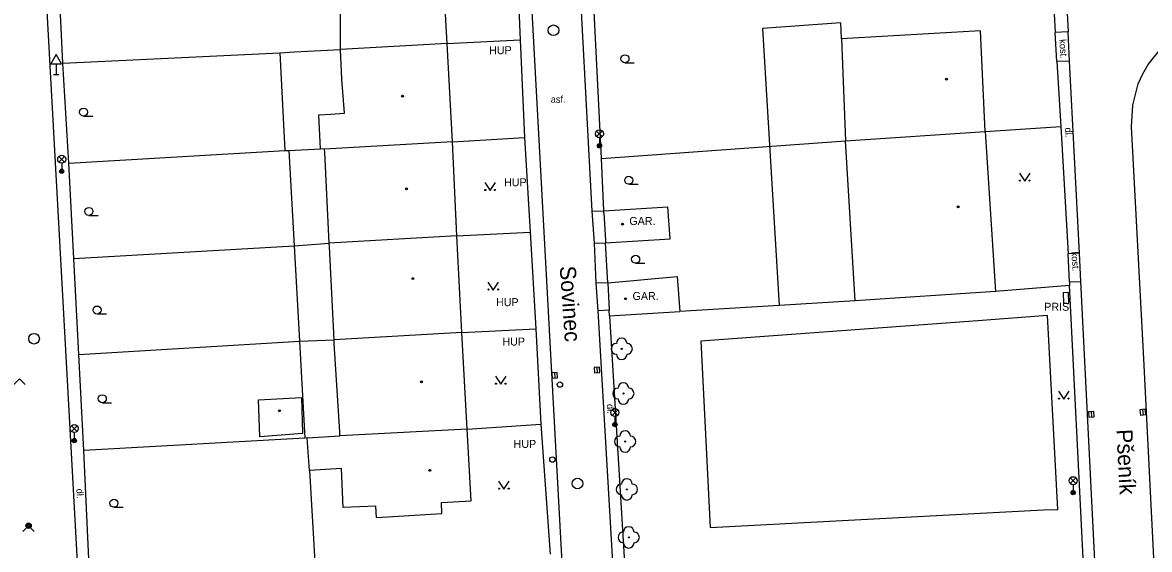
# Model space of a CAD drawing. Extents: x -599951 to -598963, y -1164095 to -1162939.
# Drawn here: x -599424.5 to -599318.9, y -1163053.4 to -1163004 of the extents above; entities that cross this region are included whole.
import ezdxf

# ---------------------------------------------------------------- set-up
doc = ezdxf.new("R2010")
doc.units = 0
for name, color, linetype in [('Level 10', 7, 'Continuous'), ('Level 11', 7, 'Continuous'), ('Level 22', 7, 'Continuous'), ('Level 24', 7, 'Continuous'), ('Level 27', 7, 'Continuous'), ('Level 31', 7, 'Continuous'), ('Level 33', 7, 'Continuous'), ('Level 34', 7, 'Continuous'), ('Level 36', 7, 'Continuous'), ('Level 39', 7, 'Continuous'), ('Level 40', 7, 'Continuous'), ('Level 41', 7, 'Continuous'), ('Level 5', 7, 'Continuous'), ('Level 50', 7, 'Continuous'), ('Level 6', 7, 'Continuous'), ('Level 7', 7, 'Continuous'), ('Level 8', 7, 'Continuous')]:
    doc.layers.add(name, color=color, linetype=linetype)

msp = doc.modelspace()

# ---------------------------------------------------------------- linework, layer by layer
at = {"layer": 'Level 10'}
for points in [[(-599329.53, -1162948.63), (-599326.52, -1163004.82)], [(-599372.79, -1163075.84), (-599377.4, -1162990.82)], [(-599371.12, -1163021.66), (-599372.6, -1162994.11)], [(-599415.69, -1163120.97), (-599422.36, -1163000.03)], [(-599326.38, -1163007.57), (-599326.52, -1163004.82)], [(-599320.58, -1163013.74), (-599320.47, -1163011.7), (-599319.95, -1163009.72), (-599319.53, -1163008.78), (-599319.02, -1163007.89), (-599317.74, -1163006.3), (-599316.15, -1163005)], [(-599325.47, -1163025.58), (-599326.38, -1163007.57)], [(-599314.2, -1163139.3), (-599316.54, -1163092.74), (-599319.44, -1163035.48), (-599320.58, -1163013.74)], [(-599370.9, -1163024.66), (-599371.12, -1163021.66)], [(-599370.74, -1163028.41), (-599370.9, -1163024.66)], [(-599325.34, -1163028.23), (-599325.47, -1163025.58)], [(-599370.55, -1163030.99), (-599370.74, -1163028.41)], [(-599319.94, -1163136.04), (-599325.34, -1163028.23)], [(-599369.05, -1163056.7), (-599370.55, -1163030.99)]]:
    msp.add_lwpolyline(points, dxfattribs=at)
at = {"layer": 'Level 11'}
for points in [[(-599347.76, -1163005.5), (-599347.82, -1163004), (-599355.17, -1163004.51), (-599353.61, -1163030.48)], [(-599326.52, -1163004.82), (-599327.74, -1163004.88)], [(-599400.39, -1163006.79), (-599399.93, -1163015.97)], [(-599326.38, -1163007.57), (-599327.58, -1163007.6)], [(-599399.54, -1163015.95), (-599399.05, -1163024.88)], [(-599371.12, -1163021.66), (-599370.03, -1163021.6)], [(-599370.9, -1163024.66), (-599369.87, -1163024.6)], [(-599399.05, -1163024.88), (-599398.54, -1163033.82)], [(-599325.47, -1163025.58), (-599326.52, -1163025.63)], [(-599369.66, -1163028.35), (-599370.74, -1163028.41)], [(-599326.4, -1163028.26), (-599325.34, -1163028.23)], [(-599325.1, -1163054.18), (-599326.39, -1163028.6)], [(-599369.52, -1163030.93), (-599370.55, -1163030.99)], [(-599369.49, -1163031.45), (-599367.96, -1163056.69)], [(-599334.98, -1163031.91), (-599360.95, -1163033.82), (-599360.07, -1163051.3), (-599328.84, -1163049.65)], [(-599328.84, -1163049.65), (-599327.49, -1163049.62), (-599328.45, -1163031.43), (-599334.98, -1163031.91)], [(-599398.54, -1163033.82), (-599398.05, -1163042.91)], [(-599397.61, -1163045.97), (-599397.09, -1163055.06)]]:
    msp.add_lwpolyline(points, dxfattribs=at)
at = {"layer": 'Level 22'}
for centre in [(-599368.36, -1163034.55), (-599368.2, -1163038.74), (-599368.04, -1163043.24), (-599367.87, -1163047.73), (-599367.7, -1163052.23)]:
    msp.add_circle(centre, 0.05, dxfattribs=at)
for centre, start, end in [((-599368.86, -1163034.55), 90, 270), ((-599368.36, -1163034.05), 0, 180), ((-599367.86, -1163034.55), 270, 90), ((-599368.36, -1163035.05), 180, 0), ((-599368.7, -1163038.74), 90, 270), ((-599368.2, -1163038.24), 0, 180), ((-599367.7, -1163038.74), 270, 90), ((-599368.2, -1163039.24), 180, 0), ((-599368.04, -1163042.74), 0, 180), ((-599368.54, -1163043.24), 90, 270), ((-599368.04, -1163043.74), 180, 0), ((-599367.54, -1163043.24), 270, 90), ((-599367.87, -1163047.23), 0, 180), ((-599368.37, -1163047.73), 90, 270), ((-599367.37, -1163047.73), 270, 90), ((-599367.87, -1163048.23), 180, 0), ((-599368.2, -1163052.23), 90, 270), ((-599367.7, -1163051.73), 0, 180), ((-599367.2, -1163052.23), 270, 90), ((-599367.7, -1163052.73), 180, 0)]:
    msp.add_arc(centre, 0.5, start, end, dxfattribs=at)
at = {"layer": 'Level 24'}
msp.add_lwpolyline([(-599326.99, -1163029.3), (-599326.97, -1163030.3), (-599326.47, -1163030.28), (-599326.49, -1163029.28)], close=True, dxfattribs=at)
at = {"layer": 'Level 27'}
for p, q in [((-599370.69, -1163036.29), (-599370.65, -1163036.79)), ((-599374.67, -1163036.78), (-599374.63, -1163037.28)), ((-599324.37, -1163040.44), (-599324.33, -1163040.94)), ((-599319.54, -1163040.24), (-599319.5, -1163040.74))]:
    msp.add_line(p, q, dxfattribs=at)
for points in [[(-599370.94, -1163036.31), (-599370.9, -1163036.81), (-599370.4, -1163036.77), (-599370.44, -1163036.27)], [(-599374.92, -1163036.8), (-599374.88, -1163037.3), (-599374.38, -1163037.26), (-599374.42, -1163036.76)], [(-599324.62, -1163040.46), (-599324.58, -1163040.96), (-599324.08, -1163040.92), (-599324.12, -1163040.42)], [(-599319.79, -1163040.26), (-599319.75, -1163040.76), (-599319.25, -1163040.72), (-599319.29, -1163040.22)]]:
    msp.add_lwpolyline(points, close=True, dxfattribs=at)
for centre in [(-599374.75, -1163004.69), (-599423.43, -1163033.6), (-599372.5, -1163047.18)]:
    msp.add_circle(centre, 0.5, dxfattribs=at)
at = {"layer": 'Level 31'}
for points in [[(-599425.31, -1163037.89), (-599424.78, -1163037.36), (-599424.25, -1163037.89)], [(-599424.47, -1163051.66), (-599423.94, -1163051.13), (-599423.41, -1163051.66)]]:
    msp.add_lwpolyline(points, dxfattribs=at)
for centre, radius in [((-599374.15, -1163037.9), 0.25), ((-599374.85, -1163044.93), 0.25), ((-599423.94, -1163051.13), 0.25), ((-599423.94, -1163051.13), 0.18), ((-599423.94, -1163051.13), 0.11)]:
    msp.add_circle(centre, radius, dxfattribs=at)
at = {"layer": 'Level 33'}
for p, q in [((-599370.71, -1163014.66), (-599370.18, -1163014.13)), ((-599370.71, -1163014.13), (-599370.18, -1163014.66)), ((-599370.44, -1163014.77), (-599370.44, -1163015.52)), ((-599421.1, -1163017.04), (-599420.57, -1163016.51)), ((-599421.1, -1163016.51), (-599420.57, -1163017.04)), ((-599420.84, -1163017.15), (-599420.84, -1163017.9)), ((-599369.25, -1163040.79), (-599368.72, -1163040.26)), ((-599369.25, -1163040.26), (-599368.72, -1163040.79)), ((-599368.99, -1163040.9), (-599368.99, -1163041.65)), ((-599419.92, -1163042.29), (-599419.39, -1163041.76)), ((-599419.92, -1163041.76), (-599419.39, -1163042.29)), ((-599419.66, -1163042.4), (-599419.66, -1163043.15)), ((-599326.32, -1163047.17), (-599325.79, -1163046.64)), ((-599326.32, -1163046.64), (-599325.79, -1163047.17)), ((-599326.05, -1163047.28), (-599326.05, -1163048.03))]:
    msp.add_line(p, q, dxfattribs=at)
for centre, radius in [((-599370.44, -1163014.39), 0.375), ((-599370.44, -1163015.52), 0.2), ((-599370.44, -1163015.52), 0.145), ((-599370.44, -1163015.52), 0.0876), ((-599420.84, -1163016.77), 0.375), ((-599420.84, -1163017.9), 0.2), ((-599420.84, -1163017.9), 0.145), ((-599420.84, -1163017.9), 0.0876), ((-599368.99, -1163040.52), 0.375), ((-599419.66, -1163042.02), 0.375), ((-599368.99, -1163041.65), 0.2), ((-599368.99, -1163041.65), 0.145), ((-599368.99, -1163041.65), 0.0876), ((-599419.66, -1163043.15), 0.2), ((-599419.66, -1163043.15), 0.145), ((-599419.66, -1163043.15), 0.0876), ((-599326.05, -1163046.91), 0.375), ((-599326.05, -1163048.03), 0.2), ((-599326.05, -1163048.03), 0.145), ((-599326.05, -1163048.03), 0.0876)]:
    msp.add_circle(centre, radius, dxfattribs=at)
at = {"layer": 'Level 34'}
for p, q in [((-599421.37, -1163007.82), (-599421.37, -1163008.84)), ((-599421.62, -1163008.84), (-599421.12, -1163008.84))]:
    msp.add_line(p, q, dxfattribs=at)
msp.add_lwpolyline([(-599421.87, -1163007.82), (-599420.87, -1163007.82), (-599421.37, -1163006.96)], close=True, dxfattribs=at)
at = {"layer": 'Level 36'}
for p, q in [((-599368.05, -1163007.73), (-599367.18, -1163007.73)), ((-599418.79, -1163012.73), (-599417.91, -1163012.73)), ((-599367.7, -1163019.12), (-599366.82, -1163019.12)), ((-599418.29, -1163022.05), (-599417.41, -1163022.05)), ((-599367.05, -1163026.52), (-599366.18, -1163026.52)), ((-599417.52, -1163031.28), (-599416.64, -1163031.28)), ((-599417.03, -1163039.61), (-599416.16, -1163039.61)), ((-599415.94, -1163049.39), (-599415.07, -1163049.39))]:
    msp.add_line(p, q, dxfattribs=at)
for points in [[(-599331.09, -1163018.08), (-599330.59, -1163018.83), (-599330.09, -1163018.08)], [(-599381.19, -1163018.96), (-599380.69, -1163019.71), (-599380.19, -1163018.96)], [(-599380.89, -1163028.29), (-599380.39, -1163029.04), (-599379.89, -1163028.29)], [(-599380.19, -1163037.12), (-599379.69, -1163037.87), (-599379.19, -1163037.12)], [(-599327.43, -1163038.51), (-599326.93, -1163039.26), (-599326.43, -1163038.51)], [(-599379.9, -1163046.95), (-599379.4, -1163047.7), (-599378.9, -1163046.95)]]:
    msp.add_lwpolyline(points, dxfattribs=at)
for centre, radius in [((-599368.05, -1163007.36), 0.375), ((-599418.79, -1163012.36), 0.375), ((-599367.7, -1163018.75), 0.375), ((-599331.04, -1163018.78), 0.05), ((-599330.14, -1163018.78), 0.05), ((-599381.14, -1163019.66), 0.05), ((-599380.24, -1163019.66), 0.05), ((-599418.29, -1163021.67), 0.375), ((-599367.05, -1163026.15), 0.375), ((-599380.84, -1163028.99), 0.05), ((-599379.94, -1163028.99), 0.05), ((-599417.52, -1163030.91), 0.375), ((-599380.14, -1163037.82), 0.05), ((-599379.24, -1163037.82), 0.05), ((-599417.03, -1163039.23), 0.375), ((-599327.38, -1163039.21), 0.05), ((-599326.48, -1163039.21), 0.05), ((-599379.85, -1163047.65), 0.05), ((-599378.95, -1163047.65), 0.05), ((-599415.94, -1163049.02), 0.375)]:
    msp.add_circle(centre, radius, dxfattribs=at)
at = {"layer": 'Level 39'}
for centre, radius in [((-599337.93, -1163009.26), 0.09), ((-599337.93, -1163009.26), 0.0398), ((-599388.91, -1163010.87), 0.09), ((-599388.91, -1163010.87), 0.0398), ((-599388.52, -1163019.56), 0.09), ((-599388.52, -1163019.56), 0.0398), ((-599336.83, -1163021.25), 0.09), ((-599336.83, -1163021.25), 0.0398), ((-599368.28, -1163022.87), 0.09), ((-599368.28, -1163022.87), 0.0398), ((-599387.92, -1163027.97), 0.09), ((-599387.92, -1163027.97), 0.0398), ((-599367.99, -1163029.85), 0.09), ((-599367.99, -1163029.85), 0.0398), ((-599387.13, -1163037.65), 0.09), ((-599387.13, -1163037.65), 0.0398), ((-599400.43, -1163040.35), 0.09), ((-599400.43, -1163040.35), 0.0398), ((-599386.34, -1163045.94), 0.09), ((-599386.34, -1163045.94), 0.0398)]:
    msp.add_circle(centre, radius, dxfattribs=at)
at = {"layer": 'Level 5'}
for points in [[(-599384.71, -1163005.94), (-599385.14, -1162998.21)], [(-599394.71, -1163006.48), (-599394.74, -1162999.21)], [(-599334.72, -1163004.75), (-599347.76, -1163005.5)], [(-599347.76, -1163005.5), (-599347.39, -1163015.06)], [(-599334.3, -1163014.17), (-599334.72, -1163004.75)], [(-599384.71, -1163005.94), (-599394.71, -1163006.48)], [(-599394.58, -1163009.26), (-599394.71, -1163006.48)], [(-599384.2, -1163015.15), (-599384.71, -1163005.94)], [(-599394.34, -1163012.47), (-599394.58, -1163009.26)], [(-599396.75, -1163012.61), (-599395.66, -1163012.55)], [(-599396.59, -1163015.81), (-599396.75, -1163012.61)], [(-599395.66, -1163012.55), (-599394.34, -1163012.47)], [(-599347.39, -1163015.06), (-599334.3, -1163014.17)], [(-599334.3, -1163014.17), (-599333.33, -1163029.17)], [(-599384.2, -1163015.15), (-599396.2, -1163015.82)], [(-599383.81, -1163023.96), (-599384.2, -1163015.15)], [(-599346.49, -1163030.05), (-599347.39, -1163015.06)], [(-599396.2, -1163015.82), (-599396.59, -1163015.81)], [(-599396.18, -1163016.16), (-599396.2, -1163015.82)], [(-599395.77, -1163024.66), (-599396.18, -1163016.16)], [(-599370.03, -1163021.6), (-599364.03, -1163021.24)], [(-599363.83, -1163024.23), (-599364.03, -1163021.24)], [(-599370.02, -1163021.8), (-599370.03, -1163021.6)], [(-599370.02, -1163021.8), (-599369.88, -1163024.4)], [(-599383.81, -1163023.96), (-599395.77, -1163024.66)], [(-599395.75, -1163025), (-599395.77, -1163024.66)], [(-599383.35, -1163033.02), (-599383.81, -1163023.96)], [(-599369.88, -1163024.4), (-599369.87, -1163024.6)], [(-599369.87, -1163024.6), (-599363.83, -1163024.23)], [(-599395.3, -1163033.72), (-599395.75, -1163025)], [(-599369.66, -1163028.35), (-599363.15, -1163027.76)], [(-599363.15, -1163027.76), (-599362.92, -1163031.05)], [(-599369.66, -1163028.35), (-599369.52, -1163030.93)], [(-599333.33, -1163029.17), (-599346.49, -1163030.05)], [(-599369.49, -1163031.45), (-599369.52, -1163030.93)], [(-599369.49, -1163031.45), (-599362.92, -1163031.05)], [(-599383.35, -1163033.02), (-599395.3, -1163033.72)], [(-599382.85, -1163042.08), (-599383.35, -1163033.02)], [(-599395.29, -1163034.06), (-599395.3, -1163033.72)], [(-599394.77, -1163042.32), (-599395.29, -1163034.06)], [(-599402.41, -1163039.33), (-599398.38, -1163039.1)], [(-599402.28, -1163042.79), (-599402.41, -1163039.33)], [(-599398.38, -1163039.1), (-599398.26, -1163042.49)], [(-599398.26, -1163042.49), (-599402.28, -1163042.79)], [(-599382.85, -1163042.08), (-599394.78, -1163042.72)], [(-599394.78, -1163042.72), (-599394.77, -1163042.32)], [(-599382.47, -1163048.8), (-599382.85, -1163042.08)], [(-599397.83, -1163042.9), (-599394.78, -1163042.72)], [(-599397.61, -1163045.97), (-599397.83, -1163042.9)], [(-599394.63, -1163045.77), (-599397.61, -1163045.97)], [(-599394.45, -1163049.41), (-599394.63, -1163045.77)], [(-599385.26, -1163048.95), (-599382.47, -1163048.8)], [(-599385.2, -1163050), (-599385.26, -1163048.95)], [(-599391.4, -1163049.3), (-599394.45, -1163049.41)], [(-599391.34, -1163050.35), (-599391.4, -1163049.3)], [(-599391.34, -1163050.35), (-599385.2, -1163050)]]:
    msp.add_lwpolyline(points, dxfattribs=at)
at = {"layer": 'Level 6'}
for points in [[(-599370.02, -1163021.8), (-599369.88, -1163024.4)], [(-599369.66, -1163028.35), (-599369.52, -1163030.93)]]:
    msp.add_lwpolyline(points, dxfattribs=at)
at = {"layer": 'Level 7'}
for points in [[(-599378.46, -1162991.74), (-599377.86, -1163005.59)], [(-599328.11, -1162997.86), (-599327.74, -1163004.88)], [(-599420.72, -1163007.77), (-599421.11, -1162999.89)], [(-599370.25, -1163016.7), (-599371.01, -1163001.66)], [(-599384.71, -1163005.94), (-599377.86, -1163005.59)], [(-599377.86, -1163005.59), (-599377.47, -1163014.75)], [(-599420.72, -1163007.77), (-599400.39, -1163006.79)], [(-599400.39, -1163006.79), (-599399.03, -1163006.71)], [(-599399.03, -1163006.71), (-599394.71, -1163006.48)], [(-599420.17, -1163017.14), (-599420.72, -1163007.77)], [(-599327.58, -1163007.6), (-599327.22, -1163013.72)], [(-599334.3, -1163014.17), (-599327.22, -1163013.72)], [(-599327.22, -1163013.72), (-599326.52, -1163025.63)], [(-599384.2, -1163015.15), (-599377.47, -1163014.75)], [(-599377.47, -1163014.75), (-599376.94, -1163023.62)], [(-599370.25, -1163016.7), (-599347.39, -1163015.06)], [(-599420.17, -1163017.14), (-599399.93, -1163015.97)], [(-599399.93, -1163015.97), (-599399.54, -1163015.95)], [(-599399.54, -1163015.95), (-599396.59, -1163015.81)], [(-599419.69, -1163026.09), (-599420.17, -1163017.14)], [(-599370.03, -1163021.6), (-599370.25, -1163016.7)], [(-599383.81, -1163023.96), (-599376.94, -1163023.62)], [(-599376.94, -1163023.62), (-599376.41, -1163032.69)], [(-599399.05, -1163024.88), (-599395.77, -1163024.66)], [(-599369.66, -1163028.35), (-599369.87, -1163024.6)], [(-599419.69, -1163026.09), (-599399.05, -1163024.88)], [(-599419.22, -1163035.08), (-599419.69, -1163026.09)], [(-599326.39, -1163028.6), (-599333.33, -1163029.17)], [(-599326.4, -1163028.26), (-599326.39, -1163028.6)], [(-599346.49, -1163030.05), (-599353.61, -1163030.48), (-599362.92, -1163031.05)], [(-599383.35, -1163033.02), (-599376.41, -1163032.69)], [(-599376.41, -1163032.69), (-599375.94, -1163041.62)], [(-599419.22, -1163035.08), (-599398.54, -1163033.82)], [(-599398.54, -1163033.82), (-599395.3, -1163033.72)], [(-599418.75, -1163044.08), (-599419.22, -1163035.08)], [(-599382.85, -1163042.08), (-599375.94, -1163041.62)], [(-599375.94, -1163041.62), (-599375.05, -1163053.8)], [(-599398.05, -1163042.91), (-599418.75, -1163044.08)], [(-599397.83, -1163042.9), (-599398.05, -1163042.91)], [(-599418.2, -1163056.26), (-599418.75, -1163044.08)]]:
    msp.add_lwpolyline(points, dxfattribs=at)
at = {"layer": 'Level 8'}
for points in [[(-599327.58, -1163007.6), (-599327.74, -1163004.88)], [(-599326.4, -1163028.26), (-599326.52, -1163025.63)]]:
    msp.add_lwpolyline(points, dxfattribs=at)

# ---------------------------------------------------------------- texts
at = {"layer": 'Level 40'}
for s, rotation, p in [('kost.', 273.45, (-599327.35, -1163005.54)), ('dl.', 272.53, (-599326.82, -1163013.82)), ('kost.', 273.45, (-599326.22, -1163025.45)), ('dl.', 272.19, (-599369.74, -1163039.73)), ('dl.', 273.24, (-599419.47, -1163047.68))]:
    msp.add_text(s, height=0.65, rotation=rotation, dxfattribs=at).set_placement(p)
msp.add_text('asf.', height=0.65, dxfattribs=at).set_placement((-599375.01, -1163011.48))
at = {"layer": 'Level 41'}
for s, p in [('HUP', (-599380.78, -1163006.93)), ('HUP', (-599379.39, -1163019.31)), ('GAR.', (-599367.64, -1163022.94)), ('HUP', (-599380.14, -1163030.55)), ('GAR.', (-599367.34, -1163029.97)), ('PRIS', (-599328.76, -1163030.98)), ('HUP', (-599379.54, -1163034.24)), ('HUP', (-599378.49, -1163043.84))]:
    msp.add_text(s, height=0.75, dxfattribs=at).set_placement(p)
at = {"layer": 'Level 50'}
for s, rotation, p in [('Sovinec', 273.9367, (-599374.17, -1163026.82)), ('Pšeník', 272.888, (-599322, -1163042.12))]:
    msp.add_text(s, height=1.5, rotation=rotation, dxfattribs=at).set_placement(p)

doc.saveas('drawing.dxf')
